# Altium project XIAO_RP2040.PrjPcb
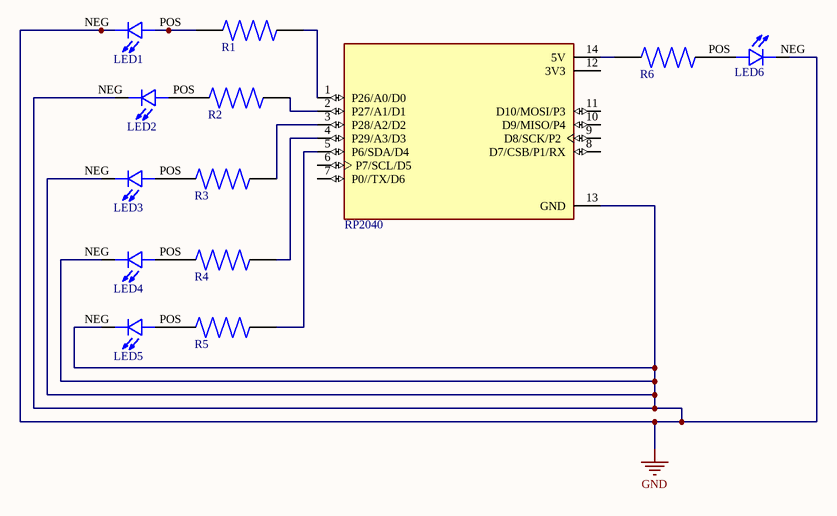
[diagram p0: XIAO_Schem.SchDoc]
1 sheet, 13 parts. Net scope: global (net labels, ports and power ports of the same name join across sheets).
Board file: PCB1.PcbDoc

## Sheet XIAO_Schem.SchDoc
size A; SheetNumber: 1; SheetTotal: 1

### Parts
LED1  LHN974_RED_LED_1206  [LED2]  (value not drawn)
LED2  LHN974_RED_LED_1206  [LED2]  (value not drawn)
LED3  LHN974_RED_LED_1206  [LED2]  (value not drawn)
LED4  LHN974_RED_LED_1206  [LED2]  (value not drawn)
LED5  LHN974_RED_LED_1206  [LED2]  (value not drawn)
LED6  LHN974_RED_LED_1206  [LED2]  (value not drawn)
R1  1k  [1k]  (value not drawn)
R2  1k  [1k]  (value not drawn)
R3  1k  [1k]  (value not drawn)
R4  1k  [1k]  (value not drawn)
R5  1k  [1k]  (value not drawn)
R6  1k  [1k]  (value not drawn)
RP2040  102010428  [102010428]  (value not drawn)

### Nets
GND: LED1.NEG LED2.NEG LED3.NEG LED4.NEG LED5.NEG LED6.NEG RP2040.13(GND)
NetLED1_POS: LED1.POS R1.1
NetLED2_POS: LED2.POS R2.1
NetLED3_POS: LED3.POS R3.1
NetLED4_POS: LED4.POS R4.1
NetLED5_POS: LED5.POS R5.1
NetLED6_POS: LED6.POS R6.2
NetR1_2: R1.2 RP2040.1(P26/A0/D0)
NetR2_2: R2.2 RP2040.2(P27/A1/D1)
NetR3_2: R3.2 RP2040.3(P28/A2/D2)
NetR4_2: R4.2 RP2040.4(P29/A3/D3)
NetR5_2: R5.2 RP2040.5(P6/SDA/D4)
NetR6_1: R6.1 RP2040.14(5V)

Not connected (* = marked no-connect by the designer): RP2040 6(P7/SCL/D5) 7(P0//TX/D6) 8(D7/CSB/P1/RX) 9(D8/SCK/P2) 10(D9/MISO/P4) 11(D10/MOSI/P3) 12(3V3)

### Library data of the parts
LED1-LED6 = LED2: 2.6 V Red LED SMD; MP: LHN974 RED LED 1206; MF: Osram
R1-R6 = 1k: Res Thick Film 3.2 x 1.6 mm 6.8K Ohm 1% 0.25W(1/4W) 100ppm/ C Molded SMD Paper T/R; MP: RC1206FR-076K8L
RP2040 = 102010428: RP2040 XIAO RP2040 series ARMÂ® CortexÂ®-M0+ MCU 32-Bit Embedded Evaluation Board; MF: Seeed Technology Co., Ltd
